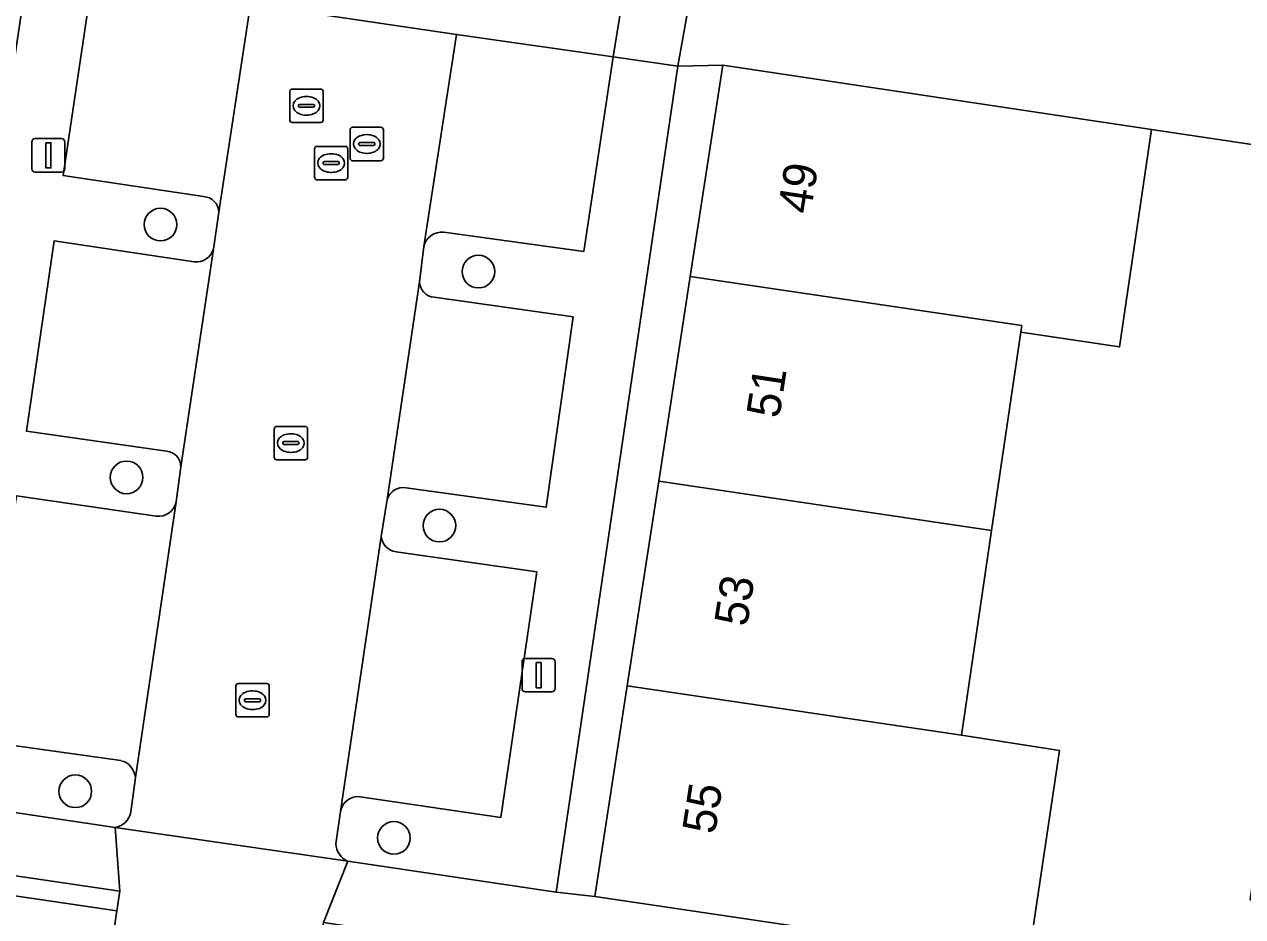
# Model space of a CAD drawing. Extents: x 164148 to 165261, y 382513 to 383432.
# Drawn here: x 164523.46 to 164559.95, y 383196.39 to 383223.11 of the extents above; entities that cross this region are included whole.
import ezdxf

# ---------------------------------------------------------------- set-up
doc = ezdxf.new("R2010")
doc.units = 0
for name, color, linetype in [('IMGEO_Boom', 7, 'Continuous'), ('IMGEO_Erf', 7, 'Continuous'), ('IMGEO_Groenvoorziening', 7, 'Continuous'), ('IMGEO_Haag', 7, 'Continuous'), ('IMGEO_Kolk', 7, 'Continuous'), ('IMGEO_Lichtmast', 7, 'Continuous'), ('IMGEO_Muur', 7, 'Continuous'), ('IMGEO_Pand', 7, 'Continuous'), ('IMGEO_Pand_nummerreeks', 7, 'Continuous'), ('IMGEO_Parkeervlak_open', 7, 'Continuous'), ('IMGEO_Rijbaan_lokaal_open', 7, 'Continuous'), ('IMGEO_Rioolput', 7, 'Continuous'), ('IMGEO_Voetpad_gesloten', 7, 'Continuous'), ('IMGEO_Voetpad_open', 7, 'Continuous')]:
    doc.layers.add(name, color=color, linetype=linetype)

msp = doc.modelspace()

# ---------------------------------------------------------------- linework, layer by layer
at = {"layer": 'IMGEO_Boom'}
for centre in [(164527.541, 383217.117), (164537.062, 383215.709), (164526.525, 383209.549), (164535.893, 383208.103), (164524.99, 383200.147), (164534.53, 383198.751)]:
    msp.add_circle(centre, 0.489, dxfattribs=at)
at = {"layer": 'IMGEO_Erf'}
for points in [[(164543.408, 383215.559), (164544.385, 383221.891), (164543.037, 383221.857), (164539.391, 383197.126), (164540.545, 383196.996), (164541.518, 383203.305), (164542.463, 383209.432)], [(164564.682, 383208.741), (164561.93, 383209.157), (164562.473, 383212.746), (164563.281, 383212.624), (164564.232, 383218.921), (164557.219, 383219.961), (164556.262, 383213.457), (164553.303, 383213.893), (164552.428, 383207.958), (164551.524, 383201.824), (164554.463, 383201.368), (164553.529, 383195.067), (164562.467, 383193.759), (164562.532, 383193.748), (164562.926, 383196.502), (164560.174, 383196.896), (164560.686, 383200.48), (164561.198, 383204.065), (164563.95, 383203.671)]]:
    msp.add_lwpolyline(points, close=True, dxfattribs=at)
at = {"layer": 'IMGEO_Groenvoorziening'}
for points in [[(164540.938, 383234.279), (164474.369, 383244.09), (164473.784, 383239.878), (164475.752, 383239.581), (164474.664, 383231.95), (164475.847, 383231.993), (164485.729, 383230.555), (164498.339, 383228.661), (164499.828, 383228.437), (164509.441, 383226.994), (164522.281, 383225.127), (164523.562, 383224.708), (164525.491, 383224.423), (164530.235, 383223.716), (164536.41, 383222.814), (164541.102, 383222.137), (164541.721, 383225.968), (164539.787, 383226.205)], [(164568.363, 383224.706), (164570.88, 383224.66), (164586.384, 383222.732), (164587.311, 383223.56), (164588.039, 383223.46), (164588.503, 383222.765), (164589.304, 383222.659), (164589.864, 383225.37), (164590.192, 383226.957), (164588.572, 383227.202), (164542.964, 383233.969), (164541.988, 383228.001), (164544.082, 383227.744), (164543.037, 383221.857), (164544.385, 383221.891), (164557.219, 383219.961), (164564.232, 383218.921), (164567.625, 383218.423), (164568.247, 383218.335)], [(164526.327, 383197.159), (164494.769, 383201.802), (164494.684, 383201.208), (164526.238, 383196.566)], [(164526.238, 383196.566), (164494.684, 383201.208), (164493.949, 383196.067), (164493.77, 383194.815), (164525.275, 383190.131), (164525.45, 383191.3)]]:
    msp.add_lwpolyline(points, close=True, dxfattribs=at)
at = {"layer": 'IMGEO_Haag'}
msp.add_lwpolyline([(164526.327, 383197.159), (164494.769, 383201.802), (164494.684, 383201.208), (164526.238, 383196.566)], close=True, dxfattribs=at)
at = {"layer": 'IMGEO_Kolk'}
for p, q in [((164532.151, 383218.535), (164532.151, 383219.387)), ((164532.226, 383219.461), (164533.078, 383219.461)), ((164533.152, 383219.387), (164533.152, 383218.535)), ((164532.41, 383218.955), (164532.41, 383218.967)), ((164532.453, 383219.004), (164532.851, 383219.004)), ((164532.639, 383219.241), (164532.664, 383219.241)), ((164532.894, 383218.967), (164532.894, 383218.955)), ((164532.848, 383218.918), (164532.45, 383218.918)), ((164532.662, 383218.681), (164532.637, 383218.681)), ((164533.078, 383218.461), (164532.226, 383218.461)), ((164530.945, 383210.15), (164530.945, 383211.002)), ((164531.02, 383211.076), (164531.872, 383211.076)), ((164531.946, 383211.002), (164531.946, 383210.15)), ((164531.204, 383210.57), (164531.204, 383210.582)), ((164531.247, 383210.619), (164531.645, 383210.619)), ((164531.433, 383210.856), (164531.458, 383210.856)), ((164531.688, 383210.582), (164531.688, 383210.57)), ((164531.642, 383210.533), (164531.244, 383210.533)), ((164531.456, 383210.296), (164531.431, 383210.296)), ((164531.872, 383210.076), (164531.02, 383210.076)), ((164529.796, 383202.448), (164529.796, 383203.3)), ((164529.871, 383203.374), (164530.723, 383203.374)), ((164530.797, 383203.3), (164530.797, 383202.448)), ((164530.055, 383202.868), (164530.055, 383202.88)), ((164530.098, 383202.917), (164530.496, 383202.917)), ((164530.284, 383203.154), (164530.309, 383203.154)), ((164530.539, 383202.88), (164530.539, 383202.868)), ((164530.493, 383202.831), (164530.095, 383202.831)), ((164530.307, 383202.594), (164530.282, 383202.594)), ((164530.723, 383202.374), (164529.871, 383202.374))]:
    msp.add_line(p, q, dxfattribs=at)
for points in [[(164532.151, 383218.535), (164532.151, 383219.387)], [(164532.226, 383219.461), (164533.078, 383219.461)], [(164533.152, 383219.387), (164533.152, 383218.535)], [(164533.078, 383218.461), (164532.226, 383218.461)], [(164530.945, 383210.15), (164530.945, 383211.002)], [(164531.02, 383211.076), (164531.872, 383211.076)], [(164531.946, 383211.002), (164531.946, 383210.15)], [(164531.872, 383210.076), (164531.02, 383210.076)], [(164529.796, 383202.448), (164529.796, 383203.3)], [(164529.871, 383203.374), (164530.723, 383203.374)], [(164530.797, 383203.3), (164530.797, 383202.448)], [(164530.723, 383202.374), (164529.871, 383202.374)]]:
    msp.add_lwpolyline(points, dxfattribs=at)
for centre, radius, start, end in [((164532.228, 383219.385), 0.0765, 91.552, 178.448), ((164532.228, 383219.385), 0.0765, 91.552, 178.448), ((164533.076, 383219.385), 0.0765, 1.552, 88.448), ((164533.076, 383219.385), 0.0765, 1.552, 88.448), ((164532.45, 383218.964), 0.0403, 85.8775, 175.7526), ((164532.447, 383218.954), 0.0366, 178.938, 274.7102), ((164532.851, 383218.961), 0.043, 264.8664, 352.4533), ((164532.855, 383218.966), 0.0386, 1.7309, 96.639), ((164532.228, 383218.537), 0.0765, 181.552, 268.448), ((164532.228, 383218.537), 0.0765, 181.552, 268.448), ((164533.076, 383218.537), 0.0765, 271.552, 358.448), ((164533.076, 383218.537), 0.0765, 271.552, 358.448), ((164531.022, 383211), 0.0765, 91.552, 178.448), ((164531.022, 383211), 0.0765, 91.552, 178.448), ((164531.87, 383211), 0.0765, 1.552, 88.448), ((164531.87, 383211), 0.0765, 1.552, 88.448), ((164531.244, 383210.579), 0.0403, 85.8775, 175.7526), ((164531.241, 383210.569), 0.0366, 178.938, 274.7102), ((164531.645, 383210.576), 0.043, 264.8664, 352.4533), ((164531.649, 383210.581), 0.0386, 1.7309, 96.639), ((164531.022, 383210.152), 0.0765, 181.552, 268.448), ((164531.022, 383210.152), 0.0765, 181.552, 268.448), ((164531.87, 383210.152), 0.0765, 271.552, 358.448), ((164531.87, 383210.152), 0.0765, 271.552, 358.448), ((164529.873, 383203.298), 0.0765, 91.552, 178.448), ((164529.873, 383203.298), 0.0765, 91.552, 178.448), ((164530.721, 383203.298), 0.0765, 1.552, 88.448), ((164530.721, 383203.298), 0.0765, 1.552, 88.448), ((164530.095, 383202.877), 0.0403, 85.8775, 175.7526), ((164530.5, 383202.879), 0.0386, 1.7309, 96.639), ((164530.092, 383202.867), 0.0366, 178.938, 274.7102), ((164530.496, 383202.874), 0.043, 264.8664, 352.4533), ((164529.873, 383202.45), 0.0765, 181.552, 268.448), ((164529.873, 383202.45), 0.0765, 181.552, 268.448), ((164530.721, 383202.45), 0.0765, 271.552, 358.448), ((164530.721, 383202.45), 0.0765, 271.552, 358.448)]:
    msp.add_arc(centre, radius, start, end, dxfattribs=at)
for centre, major_axis, ratio, start_param, end_param in [((164532.638, 383218.961), (-0.387, 0.002), 0.722429, 4.712389, 7.853982), ((164532.663, 383218.961), (-0.39, 0.002), 0.717154, 1.570796, 4.712389), ((164531.432, 383210.576), (-0.387, 0.002), 0.722429, 4.712389, 7.853982), ((164531.457, 383210.576), (-0.39, 0.002), 0.717154, 1.570796, 4.712389), ((164530.283, 383202.874), (-0.387, 0.002), 0.722429, 4.712389, 7.853982), ((164530.308, 383202.874), (-0.39, 0.002), 0.717154, 1.570796, 4.712389)]:
    msp.add_ellipse(centre, major_axis=major_axis, ratio=ratio, start_param=start_param, end_param=end_param, dxfattribs=at)
at = {"layer": 'IMGEO_Lichtmast'}
for p, q in [((164523.788, 383219.691), (164524.578, 383219.691)), ((164524.578, 383219.691), (164523.788, 383219.691)), ((164523.688, 383218.791), (164523.688, 383219.591)), ((164523.688, 383219.591), (164523.688, 383218.791)), ((164524.678, 383219.591), (164524.678, 383218.791)), ((164524.678, 383218.791), (164524.678, 383219.591)), ((164524.578, 383218.691), (164523.788, 383218.691)), ((164523.788, 383218.691), (164524.578, 383218.691)), ((164538.367, 383203.225), (164538.367, 383204.025)), ((164538.367, 383204.025), (164538.367, 383203.225)), ((164538.467, 383204.125), (164539.257, 383204.125)), ((164539.257, 383204.125), (164538.467, 383204.125)), ((164539.357, 383204.025), (164539.357, 383203.225)), ((164539.357, 383203.225), (164539.357, 383204.025)), ((164539.257, 383203.125), (164538.467, 383203.125)), ((164538.467, 383203.125), (164539.257, 383203.125))]:
    msp.add_line(p, q, dxfattribs=at)
for points in [[(164524.108, 383219.566), (164524.258, 383219.566), (164524.258, 383218.816), (164524.108, 383218.816), (164524.108, 383219.566)], [(164538.787, 383204), (164538.937, 383204), (164538.937, 383203.25), (164538.787, 383203.25), (164538.787, 383204)]]:
    msp.add_lwpolyline(points, dxfattribs=at)
for centre, start, end in [((164523.788, 383219.591), 90, 180), ((164523.788, 383219.591), 90, 180), ((164524.578, 383219.591), 0, 90), ((164524.578, 383219.591), 360, 90), ((164523.788, 383218.791), 180, 270), ((164523.788, 383218.791), 180, 270), ((164524.578, 383218.791), 270, 0), ((164524.578, 383218.791), 270, 0), ((164538.467, 383204.025), 90, 180), ((164538.467, 383204.025), 90, 180), ((164539.257, 383204.025), 0, 90), ((164539.257, 383204.025), 360, 90), ((164538.467, 383203.225), 180, 270), ((164538.467, 383203.225), 180, 270), ((164539.257, 383203.225), 270, 0), ((164539.257, 383203.225), 270, 0)]:
    msp.add_arc(centre, 0.1, start, end, dxfattribs=at)
at = {"layer": 'IMGEO_Muur'}
msp.add_lwpolyline([(164557.219, 383219.961), (164564.232, 383218.921), (164566.179, 383218.635)], dxfattribs=at)
at = {"layer": 'IMGEO_Pand'}
for points in [[(164553.303, 383213.893), (164556.262, 383213.457), (164557.219, 383219.961), (164544.385, 383221.891), (164543.408, 383215.559), (164553.333, 383214.091)], [(164542.463, 383209.432), (164552.428, 383207.958), (164553.303, 383213.893), (164553.333, 383214.091), (164543.408, 383215.559)], [(164542.463, 383209.432), (164541.518, 383203.305), (164551.524, 383201.824), (164552.428, 383207.958)], [(164551.524, 383201.824), (164541.518, 383203.305), (164540.545, 383196.996), (164550.593, 383195.514), (164553.529, 383195.067), (164554.463, 383201.368)]]:
    msp.add_lwpolyline(points, close=True, dxfattribs=at)
at = {"layer": 'IMGEO_Parkeervlak_open'}
for points in [[(164529.284, 383217.487), (164530.235, 383223.716), (164525.491, 383224.423), (164524.63, 383218.587), (164528.83, 383217.954)], [(164536.03, 383216.89), (164540.218, 383216.316), (164541.102, 383222.137), (164536.41, 383222.814), (164535.426, 383216.461)], [(164528.552, 383216.004), (164524.354, 383216.628), (164523.526, 383210.929), (164527.719, 383210.332)], [(164528.146, 383209.86), (164529.128, 383216.383)], [(164535.298, 383215.404), (164534.334, 383208.883)], [(164534.898, 383209.23), (164539.092, 383208.654), (164539.899, 383214.354), (164535.735, 383214.941)], [(164527.415, 383208.387), (164523.231, 383208.997), (164522.135, 383201.66), (164526.356, 383201.065)], [(164526.789, 383200.561), (164528.009, 383208.818)], [(164534.147, 383207.776), (164532.935, 383199.545)], [(164533.52, 383199.986), (164537.73, 383199.368), (164538.81, 383206.718), (164534.596, 383207.323)]]:
    msp.add_lwpolyline(points, dxfattribs=at)
for centre, radius, start, end in [((164528.821, 383217.491), 0.463, 359.4566, 88.926), ((164535.967, 383216.338), 0.555, 83.5317, 167.238), ((164528.616, 383216.535), 0.534, 263.1741, 343.5147), ((164535.775, 383215.417), 0.477, 181.5091, 265.1814), ((164527.688, 383209.875), 0.458, 358.1539, 86.1149), ((164534.796, 383208.763), 0.478, 77.7276, 165.4761), ((164527.482, 383208.92), 0.537, 262.8352, 349.0933), ((164534.66, 383207.835), 0.516, 186.5848, 262.907), ((164526.229, 383200.518), 0.561, 4.3871, 76.9465), ((164533.458, 383199.46), 0.53, 83.2516, 170.7698)]:
    msp.add_arc(centre, radius, start, end, dxfattribs=at)
at = {"layer": 'IMGEO_Rijbaan_lokaal_open'}
for points in [[(164532.793, 383198.578), (164532.935, 383199.545), (164534.147, 383207.776), (164534.334, 383208.883), (164535.298, 383215.404), (164535.426, 383216.461), (164536.41, 383222.814), (164530.235, 383223.716), (164529.284, 383217.487), (164529.128, 383216.383), (164528.146, 383209.86), (164528.009, 383208.818), (164526.789, 383200.561), (164526.655, 383199.533)], [(164526.18, 383199.06), (164533.153, 383198.051)]]:
    msp.add_lwpolyline(points, dxfattribs=at)
for centre, radius, start, end in [((164526.073, 383199.643), 0.592, 280.4191, 349.3391), ((164533.393, 383198.601), 0.601, 182.2375, 246.4374)]:
    msp.add_arc(centre, radius, start, end, dxfattribs=at)
at = {"layer": 'IMGEO_Rioolput'}
for p, q in [((164531.487, 383221.175), (164532.339, 383221.175)), ((164531.412, 383220.249), (164531.412, 383221.101)), ((164531.9, 383220.955), (164531.925, 383220.955)), ((164532.413, 383221.101), (164532.413, 383220.249)), ((164531.671, 383220.669), (164531.671, 383220.681)), ((164532.109, 383220.632), (164531.711, 383220.632)), ((164531.714, 383220.718), (164532.112, 383220.718)), ((164531.923, 383220.395), (164531.898, 383220.395)), ((164532.155, 383220.681), (164532.155, 383220.669)), ((164532.339, 383220.175), (164531.487, 383220.175)), ((164533.293, 383220.031), (164534.145, 383220.031)), ((164533.218, 383219.105), (164533.218, 383219.957)), ((164533.706, 383219.811), (164533.731, 383219.811)), ((164534.219, 383219.957), (164534.219, 383219.105)), ((164533.477, 383219.525), (164533.477, 383219.537)), ((164533.915, 383219.488), (164533.517, 383219.488)), ((164533.52, 383219.574), (164533.918, 383219.574)), ((164533.961, 383219.537), (164533.961, 383219.525)), ((164534.145, 383219.031), (164533.293, 383219.031)), ((164533.729, 383219.251), (164533.704, 383219.251))]:
    msp.add_line(p, q, dxfattribs=at)
for points in [[(164531.487, 383221.175), (164532.339, 383221.175)], [(164531.412, 383220.249), (164531.412, 383221.101)], [(164532.413, 383221.101), (164532.413, 383220.249)], [(164532.339, 383220.175), (164531.487, 383220.175)], [(164533.293, 383220.031), (164534.145, 383220.031)], [(164533.218, 383219.105), (164533.218, 383219.957)], [(164534.219, 383219.957), (164534.219, 383219.105)], [(164534.145, 383219.031), (164533.293, 383219.031)]]:
    msp.add_lwpolyline(points, dxfattribs=at)
for centre, radius, start, end in [((164531.489, 383221.099), 0.0765, 91.552, 178.448), ((164531.489, 383221.099), 0.0765, 91.552, 178.448), ((164532.337, 383221.099), 0.0765, 1.552, 88.448), ((164532.337, 383221.099), 0.0765, 1.552, 88.448), ((164531.711, 383220.678), 0.0403, 85.8775, 175.7526), ((164531.708, 383220.668), 0.0366, 178.938, 274.7102), ((164532.112, 383220.675), 0.043, 264.8664, 352.4533), ((164532.116, 383220.68), 0.0386, 1.7309, 96.639), ((164531.489, 383220.251), 0.0765, 181.552, 268.448), ((164531.489, 383220.251), 0.0765, 181.552, 268.448), ((164532.337, 383220.251), 0.0765, 271.552, 358.448), ((164532.337, 383220.251), 0.0765, 271.552, 358.448), ((164533.295, 383219.955), 0.0765, 91.552, 178.448), ((164533.295, 383219.955), 0.0765, 91.552, 178.448), ((164534.143, 383219.955), 0.0765, 1.552, 88.448), ((164534.143, 383219.955), 0.0765, 1.552, 88.448), ((164533.517, 383219.534), 0.0403, 85.8775, 175.7526), ((164533.514, 383219.524), 0.0366, 178.938, 274.7102), ((164533.918, 383219.531), 0.043, 264.8664, 352.4533), ((164533.922, 383219.536), 0.0386, 1.7309, 96.639), ((164533.295, 383219.107), 0.0765, 181.552, 268.448), ((164533.295, 383219.107), 0.0765, 181.552, 268.448), ((164534.143, 383219.107), 0.0765, 271.552, 358.448), ((164534.143, 383219.107), 0.0765, 271.552, 358.448)]:
    msp.add_arc(centre, radius, start, end, dxfattribs=at)
for centre, major_axis, ratio, start_param, end_param in [((164531.899, 383220.675), (-0.387, 0.002), 0.722429, 4.712389, 7.853982), ((164531.924, 383220.675), (-0.39, 0.002), 0.717154, 1.570796, 4.712389), ((164533.705, 383219.531), (-0.387, 0.002), 0.722429, 4.712389, 7.853982), ((164533.73, 383219.531), (-0.39, 0.002), 0.717154, 1.570796, 4.712389)]:
    msp.add_ellipse(centre, major_axis=major_axis, ratio=ratio, start_param=start_param, end_param=end_param, dxfattribs=at)
at = {"layer": 'IMGEO_Voetpad_gesloten'}
msp.add_lwpolyline([(164542.964, 383233.969), (164540.938, 383234.279), (164539.787, 383226.205), (164541.721, 383225.968), (164541.102, 383222.137), (164543.037, 383221.857), (164544.082, 383227.744), (164541.988, 383228.001)], close=True, dxfattribs=at)
at = {"layer": 'IMGEO_Voetpad_open'}
for points in [[(164528.83, 383217.954), (164524.63, 383218.587), (164525.491, 383224.423), (164523.562, 383224.708), (164519.882, 383199.998), (164526.18, 383199.06)], [(164533.153, 383198.051), (164539.391, 383197.126), (164543.037, 383221.857), (164541.102, 383222.137), (164540.218, 383216.316), (164536.03, 383216.89)], [(164529.128, 383216.383), (164529.284, 383217.487)], [(164527.719, 383210.332), (164523.526, 383210.929), (164524.354, 383216.628), (164528.552, 383216.004)], [(164535.426, 383216.461), (164535.298, 383215.404)], [(164535.735, 383214.941), (164539.899, 383214.354), (164539.092, 383208.654), (164534.898, 383209.23)], [(164528.009, 383208.818), (164528.146, 383209.86)], [(164526.356, 383201.065), (164522.135, 383201.66), (164523.231, 383208.997), (164527.415, 383208.387)], [(164534.334, 383208.883), (164534.147, 383207.776)], [(164534.596, 383207.323), (164538.81, 383206.718), (164537.73, 383199.368), (164533.52, 383199.986)], [(164526.655, 383199.533), (164526.789, 383200.561)], [(164532.935, 383199.545), (164532.793, 383198.578)], [(164562.467, 383193.759), (164553.529, 383195.067), (164550.593, 383195.514), (164540.545, 383196.996), (164539.391, 383197.126), (164533.153, 383198.051), (164532.423, 383196.223), (164555.292, 383192.808), (164556.788, 383192.585), (164562.196, 383191.777)]]:
    msp.add_lwpolyline(points, dxfattribs=at)
for points in [[(164494.769, 383201.802), (164526.327, 383197.159), (164526.18, 383199.06), (164519.882, 383199.998), (164518.636, 383200.305), (164505.747, 383202.144), (164496.128, 383203.54), (164494.405, 383203.79), (164491.475, 383204.203), (164485.048, 383205.215), (164472.16, 383207.129), (164470.892, 383207.305), (164464.719, 383208.19), (164463.935, 383206.398), (164491.218, 383202.312), (164491.129, 383201.718), (164490.359, 383196.569), (164493.949, 383196.067), (164494.684, 383201.208)], [(164532.332, 383195.63), (164532.423, 383196.223), (164533.153, 383198.051), (164526.18, 383199.06), (164526.327, 383197.159), (164526.238, 383196.566), (164525.45, 383191.3), (164531.536, 383190.432), (164532.276, 383195.262)]]:
    msp.add_lwpolyline(points, close=True, dxfattribs=at)
for centre, radius, start, end in [((164528.821, 383217.491), 0.463, 359.4566, 88.926), ((164535.967, 383216.338), 0.555, 83.5317, 167.238), ((164528.616, 383216.535), 0.534, 263.1741, 343.5147), ((164535.775, 383215.417), 0.477, 181.5091, 265.1814), ((164527.688, 383209.875), 0.458, 358.1539, 86.1149), ((164534.796, 383208.763), 0.478, 77.7276, 165.4761), ((164527.482, 383208.92), 0.537, 262.8352, 349.0933), ((164534.66, 383207.835), 0.516, 186.5848, 262.907), ((164526.229, 383200.518), 0.561, 4.3871, 76.9465), ((164533.458, 383199.46), 0.53, 83.2516, 170.7698), ((164526.073, 383199.643), 0.592, 280.4191, 349.3391), ((164533.393, 383198.601), 0.601, 182.2375, 246.4374)]:
    msp.add_arc(centre, radius, start, end, dxfattribs=at)

# ---------------------------------------------------------------- texts
at = {"layer": 'IMGEO_Pand_nummerreeks'}
for s, p in [('49', (164547.012, 383217.408)), ('51', (164546.069, 383211.291)), ('53', (164545.107, 383205.054)), ('55', (164544.148, 383198.836))]:
    msp.add_text(s, height=1, rotation=81.234, dxfattribs=at).set_placement(p)

doc.saveas('drawing.dxf')
